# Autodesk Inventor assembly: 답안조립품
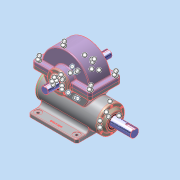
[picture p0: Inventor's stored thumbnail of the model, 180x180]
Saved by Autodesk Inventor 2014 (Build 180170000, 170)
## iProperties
Created: 2023-12
Part Number: 답안조립품
Document SubType Name: Assembly
Designer: dg
Mass: 21921.6 g
Surface Area: 7843.92 cm^2
Volume: 4928.8 cm^3
Density: 4.44767 g/cm^3
Author: dg
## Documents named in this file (14)
- C:\Users\dg\Desktop\631208V1011\답안조립품.iam
- C:\Users\dg\Desktop\631208V1011\본체.ipt
- C:\Users\dg\Desktop\631208V1011\깊은 홈 볼 베어링 6209.ipt
- C:\Users\dg\Desktop\631208V1011\웜 샤프트.ipt
- C:\Users\dg\Desktop\631208V1011\뒤커버.ipt
- C:\Users\dg\Desktop\631208V1011\앞커버.ipt
- C:\Users\dg\Desktop\631208V1011\육각 소켓 머리 볼트 M5 x 12.ipt
- C:\Users\dg\Desktop\631208V1011\오일 실 35 55 11.ipt
- C:\Users\dg\Desktop\631208V1011\깊은 홈 볼 베어링 6206.ipt
- C:\Users\dg\Desktop\631208V1011\웜 휠.ipt
- C:\Users\dg\Desktop\631208V1011\본체 커버.ipt
- C:\Users\dg\Desktop\631208V1011\육각 소켓 머리 볼트 M6 x 20.ipt
- C:\Users\dg\Desktop\631208V1011\서브커버.ipt
- C:\Users\dg\Desktop\631208V1011\오일 실 30 42 7.ipt
